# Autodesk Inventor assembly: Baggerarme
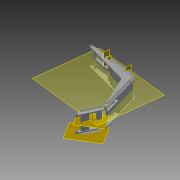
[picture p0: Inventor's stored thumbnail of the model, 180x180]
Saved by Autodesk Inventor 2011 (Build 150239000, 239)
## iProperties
Created: 2011-06
Part Number: Baggerarme
Document SubType Name: Assembly
Designer: Splendor
Author: Splendor
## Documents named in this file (3)
- C:\Users\Splendor\Desktop\Baggerarme.iam
- C:\Users\Splendor\Desktop\CAD Bagger-Projekt\Baggerarm Kurz.ipt
- C:\Users\Splendor\Desktop\CAD Bagger-Projekt\Baggerarm Lang.ipt
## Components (2 placed, 2 different names)
1. Baggerarm Kurz:1 — Passend:1, Passend:2
2. Baggerarm Lang:1 — Passend:1, Passend:2
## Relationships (2: Mate 2)
- Passend:1 [Mate]: Baggerarm Kurz:1 ↔ Baggerarm Lang:1
- Passend:2 [Mate]: Baggerarm Kurz:1 ↔ Baggerarm Lang:1
